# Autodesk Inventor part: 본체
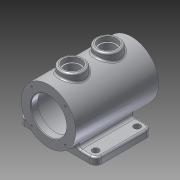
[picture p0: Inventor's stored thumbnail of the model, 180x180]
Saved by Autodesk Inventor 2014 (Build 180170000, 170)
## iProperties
Created: 2014-12
Part Number: 본체
Material: 알루미늄 6061
Document SubType Name: 판금
Designer: Owner
Mass: 1295.18 g
Surface Area: 1043.46 cm^2
Volume: 477.926 cm^3
Density: 2.71 g/cm^3
Sheet Metal Rule: 기본값
Appearance: 알루미늄 - 평지
Author: Owner
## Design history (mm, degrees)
sketch "스케치1"
  geometry: C1 r 46 at (0, 0); 1 further point
  constraints: 1 centre point, 1 coincident
  dimensions: "d0" = 92 diameter of C1
extrude "돌출1" new body sketch "스케치1" stored distance "d1" = 140; taper "d2" = 0 deg
sketch "스케치3"
  geometry: C1 r 46 at (0, 0) reference; C2 r 30 at (0, 0)
  constraints: 1 centre point, 1 coincident
  dimensions: "d6" = 60 diameter of C2
extrude "돌출3" cut sketch "스케치3" distance "d7" = 12; taper "d8" = 0 deg
sketch "스케치4"
  geometry: C1 r 30 at (0, 0) reference; C2 r 37.5 at (0, 0)
  constraints: 1 centre point, 1 coincident
  dimensions: "d9" = 75 diameter of C2
extrude "돌출4" cut sketch "스케치4" distance "d10" = 116; taper "d11" = 0 deg
sketch "스케치5"
  geometry: C1 r 46 at (0, 0) reference; C2 r 30 at (0, 0)
  constraints: 1 centre point, 1 coincident
  dimensions: "d12" = 60 diameter of C2
extrude "돌출5" cut sketch "스케치5" distance "d13" = 12; taper "d14" = 0 deg
node "작업 평면1"
sketch "스케치6"
  geometry: L1 (65, 40)-(-65, 40); L2 (-65, 40)-(-65, -55); L3 (-65, -55)-(65, -55); L4 (65, -55)-(65, 40); L5 (-46, -70)-(46, -70) reference; L6 (46, 70)-(-46, 70) reference; 3 further points
  constraints: 8 end point, 2 midpoint, 2 parallel, 2 vertical alignment, 1 horizontal, 1 perpendicular
  dimensions: "d16" = 130 distance of L2.end L3.end; "d17" = 95 distance of L1.end L2.end; "d18" = 15 vertical distance of L2.end L5.start
extrude "돌출6" join sketch "스케치6" distance "d19" = 12; taper "d20" = 0 deg
node "작업 평면2"
sketch "스케치8"
  geometry: L1 (46, 70)-(-46, 70) reference; C1 r 20 at (0, 30); C2 r 20 at (0, -30); 1 further point
  constraints: 2 centre point, 2 vertical alignment
  dimensions: "d24" = 40 distance from line of L1 C1.centre; "d25" = 40 diameter of C1; "d26" = 40 diameter of C2; "d27" = 60 distance of C1.centre C2.centre
extrude "돌출7" join sketch "스케치8" stored distance "d28" = 12; taper "d29" = 0 deg
sketch "스케치9"
  geometry: C1 r 20 at (0, 0) reference; C2 r 15 at (0, 0); 1 further point
  constraints: 1 centre point, 1 coincident
  dimensions: "d30" = 30 diameter of C2
extrude "돌출8" cut sketch "스케치9" distance "d31" = 8; taper "d32" = 0 deg
sketch "스케치10"
  geometry: C1 r 15 at (0, 0) reference; C2 r 12.5 at (0, 0); 1 further point
  constraints: 1 centre point, 1 coincident
  dimensions: "d33" = 25 diameter of C2
extrude "돌출9" cut sketch "스케치10" stored distance "d34" = 8; taper "d35" = 0 deg
sketch "스케치11"
  geometry: L1 (0, 0)-(28.284, 28.284); L2 (0, 0)-(40, 0); C1 r 46 at (0, 0) reference; 1 further point
  constraints: 4 end point, 1 coincident, 1 equal length, 1 horizontal
  dimensions: "d36" = 40 distance of L1.start L1.end; "d37" = 45 deg angle of L2 L1
hole "구멍1" sketch "스케치11" at (28.284, 28.284) diameter "d38" = 3.242; stored, may be unused: countersink angle "d42" = 90 deg, drill point angle "d44" = 118 deg; dims "d39" = 8, "d40" = 4, "d41" = 2, "d43" = 10
sketch "스케치12"
  geometry: C1 r 5.5 at (52, 27.5); 2 further points
  constraints: 1 centre point
  dimensions: "d48" = 12.5 vertical distance of point (65, 40) C1.centre; "d49" = 52 horizontal distance of C1.centre point (0, 0); "d50" = 11 diameter of C1
extrude "돌출10" cut sketch "스케치12" stored distance "d51" = 8; taper "d52" = 0 deg
sketch "스케치13"
  geometry: C1 r 5.5 at (52, 27.5) reference; C2 r 5.5 at (52, -42.5); 1 further point
  constraints: 1 centre point, 1 vertical alignment
  dimensions: "d53" = 11 diameter of C2; "d54" = 70 distance of C1.centre C2.centre
extrude "돌출11" cut sketch "스케치13" stored distance "d55" = 8; taper "d56" = 0 deg
fillet "모깎기1" dims "d57" = 10
fillet "모깎기2" dims "d58" = 5
fillet "모깎기3" dims "d59" = 3
fillet "모깎기4" dims "d60" = 3
fillet "모깎기5" dims "d61" = 3
chamfer "모따기1" distance "d62" = 1; stored, may be unused: second distance "d63" = 2, angle "d64" = 45 deg
sketch "스케치16"
  geometry: L1 (-65, 30)-(-65, -45) reference; C1 r 5.5 at (-52, 27.5) reference; 2 further points
  constraints: 1 other
  dimensions: "d65" = 35 vertical distance of point (-57, -7.5) C1.centre; "d70" = 8 distance from line of L1 point (-57, -7.5)
feature "엠보싱1" sketch "스케치16" dims "d67" = 1, "d68" = 0
fillet "모깎기6" dims "d69" = 3
node "솔리드1"
mirror "대칭1"
mirror "대칭2"
pattern_circular "원형 패턴1" dims angle "d46" = 360 deg
mirror "대칭3"
mirror "대칭4"
mirror "대칭5"
node "투영된 루프1"
other parameters: "d23" = 56, "K계수" = 4.4, "BendRadius" = 0.5 (derived), "BendReliefWidth" = 0.5 (derived), "BendReliefDepth" = 0.25 (derived), "CornerReliefSize" = 2 (derived), "SeamGap" = 0.01, "MinimumRemnant" = 1 (derived), "TransitionRadius" = 0.5 (= BendRadius)
